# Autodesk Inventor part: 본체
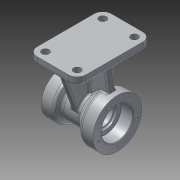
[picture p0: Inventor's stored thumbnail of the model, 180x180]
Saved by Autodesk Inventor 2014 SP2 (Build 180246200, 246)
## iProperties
Created: 2015-08
Part Number: 본체
Material: 알루미늄 6061
Document SubType Name: Modeling
Designer: 이준우
Density: 2.71 g/cm^3
Appearance: 알루미늄 - 평지
Mass: 1041.82 g
Surface Area: 749.954 cm^2
Volume: 384.434 cm^3
Author: 이준우
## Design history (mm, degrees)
sketch "스케치3"
  geometry: L1 (0, 0)-(45, 0); L2 (45, 0)-(45, 40); L3 (45, 40)-(25, 40); L4 (25, 40)-(8.199, 25.903); L5 (0, 0)-(-45, 0); L6 (-45, 0)-(-45, 35); L7 (-45, 35)-(-25, 35); L8 (-25, 35)-(-19.804, 26); L9 (0, 26)-(-19.804, 26); L10 (0, 26)-(8.315, 26)
  constraints: 20 end point, 3 perpendicular, 1 collinear, 1 horizontal, 1 parallel, 1 point on line
  dimensions: "d27" = 45 distance of L1.start L1.end; "d28" = 40 distance of L1.end L2.end; "d29" = 20 distance of L2.end L3.end; "d30" = 45 distance of L1.start L5.end; "d31" = 35 distance of L5.end L6.end; "d32" = 20 distance of L6.end L7.end; "d33" = 26 distance of L1.start L9.start; "d34" = 60 deg angle of L9 L8
revolve "회전1" sketch "스케치3" stored, may be unused: angle "d36" = 90 deg
hole "구멍1" diameter "d39" = 38; stored, may be unused: countersink angle "d43" = 90 deg, drill point angle "d45" = 0 deg; dims "d40" = 6, "d41" = 52, "d42" = 20, "d44" = 23, "d124" = 10, "d125" = 10
hole "구멍2" diameter "d48" = 32; stored, may be unused: countersink angle "d52" = 90 deg, drill point angle "d54" = 0 deg; dims "d49" = 6, "d50" = 40, "d51" = 17, "d53" = 23, "d101" = 10, "d102" = 10
node "작업 평면1"
sketch "스케치4"
  geometry: L1 (40, 0)-(40, 61); L2 (40, 61)-(-40, 61); L3 (-40, 61)-(-40, -61); L4 (-40, -61)-(40, -61); L5 (40, -61)-(40, 0); 1 further point
  constraints: 10 end point, 1 parallel
  dimensions: "d61" = 61 distance of L1.start L1.end; "d62" = 80 distance of L1.end L2.end; "d63" = 122 distance of L2.end L3.end; "d64" = 80 distance of L3.end L4.end
extrude "돌출1" join sketch "스케치4" distance "d65" = 12; taper "d66" = 0 deg
sketch "스케치5"
  geometry: L1 (-40, 61)-(40, 61) reference; L2 (40, -61)-(-40, -61) reference; L3 (-40, -61)-(-40, 61) reference; L4 (40, 61)-(40, -61) reference; L5 (0, 61)-(0, 51); L6 (0, 51)-(-6, 51); L7 (0, 51)-(6, 51); L8 (-40, 0)-(-30, 0); L9 (-30, 0)-(-30, -6); L10 (-30, 0)-(-30, 6); L11 (-74, 0)-(102, 0); L12 (0, -51)-(6, -51); L13 (0, -51)-(-6, -51); L14 (0, 0)-(0, -69); L15 (30, 0)-(30, -6); L16 (30, 0)-(30, 6); L17 (-6, 51)-(-6, -6); L18 (-6, -6)-(-6, -51); L19 (-30, -6)-(-6, -6); L20 (-6, -6)-(30, -6); L21 (-30, 6)-(-6, 6); L22 (-6, 6)-(30, 6); L23 (6, 51)-(6, 6); L24 (6, 6)-(6, -51)
  constraints: 40 end point, 13 perpendicular, 7 parallel, 6 symmetric about line, 2 midpoint, 2 point on line
  dimensions: "d67" = 10 distance of L5.start L5.end; "d68" = 6 distance of L5.end L6.end; "d69" = 6 distance of L5.end L7.end; "d70" = 10 distance of L8.start L8.end; "d71" = 6 distance of L8.end L9.end; "d72" = 6 distance of L8.end L10.end
extrude "돌출2" join sketch "스케치5" stored distance "d73" = 12; taper "d74" = 0 deg
sketch "스케치6"
  geometry: L1 (61, 78)-(-61, 78) reference; L2 (-61, 78)-(-51, 78); L3 (-51, 78)-(-25.091, 6.815); L4 (0, 0)-(0, -77); L5 (51, 78)-(25.091, 6.815); L6 (-51, 78)-(51, 78); C1 r 40 at (0, 0) reference; A1 r 26 centre (0, 0) between (0, -26) and (25.091, 6.815); A2 r 26 centre (0, 0) between (-25.091, 6.815) and (0, -26); A3 r 26 centre (0, 0) between (25.091, 6.815) and (-25.091, 6.815); 1 further point
  constraints: 10 end point, 6 point on circle, 3 centre point, 2 point on line, 2 symmetric about line, 1 coincident, 1 collinear, 1 perpendicular, 2 other
  dimensions: "d75" = 10 distance of L1.end L2.end; "d76" = 70 deg angle of L1 L3
extrude "돌출3" join sketch "스케치6" stored distance "d77" = 10; taper "d78" = 0 deg
sketch "스케치7"
  geometry: L1 (-74, 0)-(-74, 47); L2 (-74, 47)-(79, 47); L3 (0, -68)-(-26, -68); L4 (-26, -68)-(-26, 108); C1 r 6 at (-26, 47); 1 further point
  constraints: 8 end point, 2 perpendicular, 2 point on line, 1 centre point, 1 parallel, 1 vertical
  dimensions: "d80" = 47 distance of L1.start L1.end; "d81" = 26 distance of L3.start L3.end; "d82" = 12 diameter of C1
extrude "돌출4" cut sketch "스케치7" stored distance "d83" = 10; taper "d84" = 0 deg
feature "면 기울기2" dims angle "d86" = 10 deg
sketch "스케치8" dims "d87" = 66
  geometry: 4 further points
  constraints: 1 coincident, 1 horizontal alignment, 2 other
hole "구멍3" sketch "스케치8" at (33, 0) diameter "d88" = 3.242; stored, may be unused: countersink angle "d92" = 90 deg, drill point angle "d94" = 118 deg; dims "d89" = 10, "d90" = 52, "d91" = 20, "d93" = 13
sketch "스케치9" dims "d98" = 54
  geometry: 3 further points
  constraints: 1 coincident, 1 horizontal alignment, 2 other
hole "구멍4" sketch "스케치9" at (-27, 0) diameter "d103" = 3.242; stored, may be unused: countersink angle "d107" = 90 deg, drill point angle "d109" = 118 deg; dims "d104" = 10, "d105" = 52, "d106" = 20, "d108" = 13
sketch "스케치10"
  geometry: L1 (0, 0)-(0, -24); L2 (0, -24)-(119, -24); L3 (78, -61)-(60, -61); L4 (60, -61)-(60, -7); L5 (60, -24)-(54, -24); L6 (60, -18)-(54, -18); L7 (54, -30)-(60, -30); A1 r 6 centre (60, -24) between (60, -30) and (60, -18); A2 r 6 centre (54, -24) between (54, -18) and (54, -30); 1 further point
  constraints: 16 end point, 4 point on circle, 4 tangent, 3 point on line, 2 centre point, 2 parallel, 2 perpendicular, 1 midpoint, 1 vertical
  dimensions: "d114" = 24 distance of L1.start L1.end; "d115" = 18 distance of L3.start L3.end; "d118" = 6 distance of L5.start L5.end; "d119" = 12 diameter of A2
extrude "돌출5" cut sketch "스케치10" stored distance "d120" = 10; taper "d121" = 0 deg
fillet "모깎기1" dims "d122" = 5
fillet "모깎기2" dims "d123" = 0.3
fillet "모깎기3" dims "d126" = 3
fillet "모깎기4" dims "d127" = 14
fillet "모깎기5" dims "d128" = 3
fillet "모깎기6" dims "d129" = 3
fillet "모깎기7" dims "d130" = 3
fillet "모깎기8" dims "d131" = 3
fillet "모깎기9" dims "d132" = 3
fillet "모깎기10" dims "d133" = 3
fillet "모깎기11" dims "d134" = 3
fillet "모깎기12" dims "d135" = 3
fillet "모깎기13" dims "d136" = 3
fillet "모깎기14" dims "d137" = 3
chamfer "모따기1" distance "d138" = 1; stored, may be unused: second distance "d139" = 2, angle "d140" = 45 deg
sketch "스케치11"
  geometry: L1 (6.612, 0.965)-(6.612, 43.965); L2 (6.612, 43.965)-(17.612, 43.965); L3 (17.612, 43.965)-(17.612, 0.965); L4 (17.612, 0.965)-(6.612, 0.965); L5 (-3, 38.132)-(-3, 0) reference; 4 further points
  constraints: 2 midpoint, 1 horizontal alignment, 1 vertical alignment, 2 other
feature "엠보싱1" sketch "스케치11" dims "d27" = 45, "d28" = 40, "d29" = 20, "d30" = 45, "d31" = 35, "d32" = 20, "d33" = 26, "d34" = 60 deg, "d144" = 0.5, "d145" = 0
node "솔리드1"
mirror "대칭1"
mirror "대칭2"
pattern_circular "원형 패턴1" dims angle "d96" = 360 deg
pattern_circular "원형 패턴2" dims angle "d111" = 360 deg
mirror "대칭3"
other parameters: "d35" = 40 deg
